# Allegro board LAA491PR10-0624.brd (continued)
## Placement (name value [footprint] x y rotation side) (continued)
PC521  -  [C_0402]  116.02 144.14 90 bottom
PC522  -  [C_0402]  85.46 139.95 180 bottom
PC523  -  [C_0402]  83.49 135.41 90 top
PC600  -  [C_0805]  217.87 98.24 0 top
PC601  -  [C_0402]  216.62 92.66 0 bottom
PC602  -  [C_0805]  217.87 96.21 0 top
PC603  -  [C_0402]  220.06 93.37 270 top
PC604  -  [C_0402]  222.16 88.02 180 bottom
PC605  -  [C_0805]  217.14 89.96 90 bottom
PC701  -  [C_0603]  143.03 169.17 270 bottom
PC702  -  [C_0402]  143.81 166.63 180 bottom
PC703  -  [C_0805]  157.7 166.24 0 top
PC704  -  [C_0805]  157.7 164.46 0 top
PC705  -  [C_0402]  158 168.86 0 top
PC706  -  [C_0603]  157.83 167.78 0 top
PC707  -  [C_0603]  167.42 167.65 0 bottom
PC708  -  [C_0402]  166.4 167.46 90 bottom
PC709  -  [C_0603]  164.68 172.54 180 top
PC710  -  [C_0603]  163.92 167.08 180 top
PC711  -  [C_0402]  172.25 168.09 180 top
PC712  -  [C_0805]  146.63 179.72 0 top
PC713  -  [C_0805]  146.63 181.43 0 top
PC714  -  [C_0805]  145.93 175.97 0 top
PC715  -  [C_0402]  154.13 176.5 0 top
PC716  -  [C_0805]  146.63 183.14 0 top
PC717  -  [C_0402]  167.75 165.94 180 top
PC718  -  [C_0805]  145.93 174.25 0 top
PC719  -  [C_0402]  169.64 174.06 270 top
PC720  -  [C_0402]  195.61 51.71 270 bottom
PC721  -  [C_0603]  162.53 168.35 0 top
PC722  -  [C_0402]  167.73 175.14 0 top
PC723  -  [C_0402]  171.99 177.11 180 top
PC724  -  [C_EEEFZ1E101P]  157.1 164.03 0 bottom
PC803  -  [C_0603]  207.1 61.73 90 bottom
PC804  -  [C_0805]  212.73 71.83 0 top
PC805  -  [C_0805]  212.73 69.54 0 top
PC806  -  [C_0402]  204.23 51.95 0 bottom
PC807  -  [C_0603]  202.47 61.67 0 bottom
PC808  -  [C_0805]  212.73 67.26 0 top
PC809  -  [C_0402]  201.51 54.63 270 bottom
PC810  -  [C_0603]  201.51 57.48 180 top
PC811  -  [C_0603]  205.32 58.94 0 top
PC813  -  [C_0402]  205.32 55.27 270 top
PC814  -  [C_0402]  204.23 51.06 0 bottom
PC815  -  [C_0603]  208.56 62.81 0 top
PC816  -  [C_0402]  201.58 55.5 90 top
PC817  -  [C_0402]  201.58 51.05 90 bottom
PC818  -  [C_0402]  206.04 53.73 180 bottom
PC819  -  [C_0402]  199.11 59.26 180 bottom
PC820  -  [C_0402]  199.11 58.37 180 bottom
PC821  -  [C_0402]  201.59 54.62 180 top
PC831  -  [C_0402]  213.38 74.05 0 top
PC832  -  [C_0402]  213.38 73.16 0 top
PC835  -  [C_0603]  194.53 89.16 90 top
PC836  -  [C_D1]  204.04 84.58 0 top
PC837  -  [C_D1]  200.82 86.25 270 bottom
PC838  -  [C_D1]  195.99 84.68 270 bottom
PC839  -  [C_D1]  191.23 84.68 270 bottom
PC840  -  [C_0402]  181.44 122.2 0 top
PC841  -  [C_0402]  181.5 117.69 0 top
PC842  -  [C_0402]  182.08 118.93 90 top
PC843  -  [C_0402]  179.54 117.69 0 top
PC844  -  [C_0402]  177.34 117.24 180 top
PC845  -  [C_0402]  177.34 118.7 180 top
PC846  -  [C_0402]  176.49 120.67 0 top
PC847  -  [C_0402]  179.59 115.96 0 top
PC848  -  [C_0402]  181.37 115.96 0 top
PC849  -  [C_0402]  173.88 102.2 270 bottom
PC850  -  [C_0402]  178.21 119.85 270 top
PC851  -  [C_0402]  179.09 119.45 0 top
PC852  -  [C_0402]  178.73 115.71 180 top
PC853  -  [C_0402]  175.43 120.67 180 top
PC854  -  [C_0402]  174.46 117.24 0 top
PC855  -  [C_0402]  175.43 122.13 180 top
PC856  -  [C_0402]  179.28 122.2 0 top
PC857  -  [C_0402]  179.34 123.66 0 top
PC858  -  [C_0402]  181.44 123.66 0 top
PC859  -  [C_0402]  179.28 120.74 0 top
PC860  -  [C_0402]  181.44 120.74 0 top
PC861  -  [C_0402]  176.95 115.71 180 top
PC862  -  [C_0402]  178.2 112.47 0 top
PC863  -  [C_0402]  175.17 115.71 180 top
PC864  -  [C_0402]  176.36 122.13 0 top
PC865  -  [C_0402]  176.49 123.63 0 top
PC866  -  [C_0402]  174.46 118.7 0 top
PC867  -  [C_0603]  192.82 89.16 90 top
PC868  -  [C_0603]  196.31 89.16 90 top
PC869  -  [C_0402]  207.62 56.21 180 top
PC870  -  [C_0603]  198.02 89.16 90 top
PC871  -  [C_0402]  173.58 117.55 90 top
PC872  -  [C_0402]  172.18 117.02 90 top
PC873  -  [C_0402]  172.18 119.73 270 top
PC901  -  [C_0805]  97.44 122.73 90 top
PC902  -  [C_0805]  100.3 122.67 90 top
PC903  -  [C_0805]  102.77 122.67 90 top
PC904  -  [C_0805]  105.31 122.67 90 top
PC905  -  [C_0805]  107.79 122.67 90 top
PC906  -  [C_0805]  110.33 122.67 90 top
PC907  -  [C_0805]  112.81 122.67 90 top
PC908  -  [C_0805]  96.93 117.9 90 top
PC909  -  [C_0805]  100.65 137.55 0 top
PC910  -  [C_0805]  96.87 114.79 90 top
PC911  -  [C_0805]  97.35 135.33 0 top
PC912  -  [C_0805]  110.81 135.33 0 top
PC913  -  [C_0805]  110.75 137.49 0 top
PC914  -  [C_0805]  107.45 135.33 0 top
PC915  -  [C_0805]  107.38 137.49 0 top
PC916  -  [C_0805]  104.08 135.33 0 top
PC917  -  [C_0805]  100.71 135.33 0 top
PC918  -  [C_0805]  110.81 133.93 0 bottom
PC919  -  [C_0805]  107.45 133.93 0 bottom
PC920  -  [C_0805]  104.08 133.93 0 bottom
PC921  -  [C_0805]  100.71 133.93 0 bottom
PC922  -  [C_0805]  103.95 137.55 0 top
PC923  -  [C_0805]  97.35 133.93 0 bottom
PC1001  -  [C_0402]  39.14 105.74 270 bottom
PC1002  -  [C_0805]  42.95 110.53 90 bottom
PC1003  -  [C_0402]  38 116.41 270 bottom
PC1004  -  [C_0402]  36.48 105.74 270 bottom
PC1005  -  [C_0805]  40.83 115.25 0 bottom
PC1100  -  [C_0402]  178.64 173.37 0 top
PC1101  -  [C_0402]  178.64 174.25 0 top
PC1102  -  [C_0805]  178.82 175.59 0 top
PC1103  -  [C_0603]  183.16 170.25 90 top
PC1104  -  [C_0402]  188.19 172.03 180 bottom
PC1105  -  [C_0603]  183.67 173.05 90 top
PC1106  -  [C_0402]  181.45 170.11 90 top
PC1108  -  [C_APXK6R3ARA221MF451]  182.65 167.14 0 bottom
PC1200  -  [C_0402]  183.99 186.18 90 bottom
PC1201  -  [C_0805]  190.85 185.34 90 bottom
PC1202  -  [C_0805]  177.8 177.49 0 bottom
PC1203  -  [C_0402]  175.88 182.71 180 bottom
PC1204  -  [C_0805]  177.8 179.21 0 bottom
PC1205  -  [C_0603]  176.37 183.78 180 bottom
PC1206  -  [C_0805]  189.07 185.34 90 bottom
PC1207  -  [C_0805]  189.07 177.01 270 bottom
PC1209  -  [C_0402]  175.88 181.82 180 bottom
PC1210  -  [C_0603]  175.81 186.52 270 bottom
PC1211  -  [C_0805]  190.78 177.01 270 bottom
PC1212  -  [C_0603]  181.13 176.16 90 bottom
PC1213  -  [C_0603]  178.22 185.12 90 bottom
PC1214  -  [C_0402]  173.46 184.16 180 bottom
PC1300  -  [C_0805]  199.1 73.38 270 top
PC1301  -  [C_0805]  195 60.72 180 bottom
PC1302  -  [C_0402]  194.67 62.62 180 top
PC1303  -  [C_0805]  193.64 73.38 270 top
PC1304  -  [C_0402]  197.15 65.03 180 top
PC1305  -  [C_0805]  197.32 73.38 270 top
PC1306  -  [C_0402]  197.77 63.52 270 top
PC1307  -  [C_0402]  196.94 65.11 270 bottom
PC1308  -  [C_0805]  195.55 73.38 270 top
PD1  -  [IP4223CZ6_SO6]  142.24 185.05 270 bottom
PD2  -  [TVNST52302AB0_SOT523-3]  139.74 181.94 180 top
PD3  -  [TVNST52302AB0_SOT523-3]  144.07 185.19 270 bottom
PD101  -  [L03ESDL5V0CG3-2_SOT-523-3]  122.63 13.98 90 top
PD701  -  [RB751V-40_SOD323-2]  162.54 171.02 0 top
PH1  -  [R_0402]  106.19 113.74 0 top
PH501  -  [R_0402]  95.58 143.46 0 bottom
PH502  -  [R_0402]  111.93 144.16 180 bottom
PH800  -  [R_0402]  203.86 79.08 270 bottom
PJP100  -  [JUMP_43X118]  134.78 13.39 270 bottom
PJP101  -  [JUMP_43X118]  122.58 13.51 270 bottom
PJP102  -  [JUMP_43X118]  140.05 13.39 270 bottom
PJP103  -  [JUMP_43X118]  117.31 13.51 270 bottom
PJP200  -  [JUMP_43X118]  149.32 27.84 90 top
PJP201  -  [JUMP_43X118]  144.81 27.59 90 bottom
PJP203  -  [JUMP_43X39]  155.03 29.36 270 bottom
PJP300  -  [JUMP_43X118]  143.67 140.45 270 top
PJP400  -  [JUMP_43X79]  108.3 20.35 90 bottom
PJP401  -  [JUMP_43X79]  112.11 31.27 90 bottom
PJP600  -  [JUMP_43X79]  213.98 90.82 0 bottom
PJP601  -  [JUMP_43X79]  215.29 96.76 270 top
PJP1000  -  [JUMP_43X79]  42.19 104.48 90 bottom
PJP1001  -  [JUMP_43X79]  36.65 115.95 180 top
PJP1100  -  [JUMP_43X118]  182.78 162.32 270 bottom
PJP1101  -  [JUMP_43X118]  188.12 162.32 270 bottom
PJP1200  -  [JUMP_43X118]  192.27 181.37 0 bottom
PJP1300  -  [JUMP_43X79]  195.74 76.19 270 top
PJP1301  -  [JUMP_43X79]  194.66 58.76 270 bottom
PJPDC  -  [ACES_50299-00501-003_5P]  136.9 178.4 270 bottom
PL1  -  [CHT_C8BBPH853025_2P]  140.43 174 270 bottom
PL2  -  [CHT_C8BBPH853025_2P]  132.93 182.51 180 bottom
PL3  -  [CHENG_SMB3025500YA_2P]  155.86 180.26 90 bottom
PL4  -  [CHT_C8BBPH853025_2P]  132.87 166.13 180 bottom
PL100  -  [VISHAY_IHLP-2525CZ-01_2P]  135.35 25.41 0 bottom
PL101  -  [VISHAY_IHLP-2525CZ-01_2P]  120.17 25.57 180 bottom
PL102  -  [CYNTE_PCMB053T-1R0MS_2P]  127.73 31.78 270 bottom
PL200  -  [TAI-T_VMPI0703AR-1R0M-Z01_2P]  145.4 15.12 0 bottom
PL201  -  [L_1812-1806]  165.32 20.69 270 bottom
PL301  -  [CYNTE_PCMB063T-1R0MS_2P]  144.08 150.59 270 bottom
PL302  -  [L_1812-1806]  134.42 158.32 0 bottom
PL400  -  [TAIYO_NRS4018T1R0NDGJ_2P]  107.58 28.97 90 bottom
PL501  -  [L_1812-1806]  135.09 146.53 90 bottom
PL502  -  [TOKO_FDUE1040J-H-R36M-P3_4P]  109.67 140.15 180 bottom
PL600  -  [TAIYO_NRS4018T1R0NDGJ_2P]  219.55 94.6 90 bottom
PL701  -  [TOKO_FDVE1040-H-2R2M-P3_2P]  155.38 172.6 180 bottom
PL702  -  [CYNTE_PCMB053T-1R0MS_2P]  146.89 163.46 0 bottom
PL800  -  [L_1812-1806]  217.55 77.92 180 top
PL802  -  [MAG_MMD-12CE-R36M-M1L_2P]  211.17 74.49 90 bottom
PL1100  -  [TAI-T_HCB2012KF-121T50_2P]  175.16 177.38 90 top
PL1101  -  [PANAS_ETQP3W2R2WFN_2P]  176.62 169.83 90 bottom
PL1200  -  [CYNTE_PCMB063T-1R0MS_2P]  183.29 181.24 0 bottom
PL1201  -  [L_1812-1806]  171.44 178.76 0 bottom
PL1300  -  [VISHAY_IHLP-2525CZ-01_2P]  195.55 71.38 90 bottom
PQ1  -  [2N7002DW-T-R7_SOT363-6]  128.22 173.52 0 top
PQ2  -  [2N7002DW-T-R7_SOT363-6]  128.9 168.81 270 top
PQ3  -  [2N7002DW-T-R7_SOT363-6]  128.96 163.6 270 top
PQ4  -  [SSM3K7002FU_SC70-3]  128.17 179.34 0 top
PQ5  -  [RHU002N06_SOT323-3]  133.89 187.37 0 bottom
PQ6  -  [FDV301N_NL_SOT23-3]  128.97 186.57 90 bottom
PQ101  -  [SIS412DN-T1-GE3_POWERPAK8-5]  133.1 26.55 90 top
PQ102  -  [SIS412DN-T1-GE3_POWERPAK8-5]  130.23 24.72 270 top
PQ103  -  [SIS412DN-T1-GE3_POWERPAK8-5]  121.78 28.7 270 top
PQ104  -  [SIS412DN-T1-GE3_POWERPAK8-5]  124.65 22.93 90 top
PQ200  -  [SIS412DN-T1-GE3_POWERPAK8-5]  154.68 16.29 90 bottom
PQ201  -  [SIS412DN-T1-GE3_POWERPAK8-5]  157.04 14.46 270 bottom
PQ701  -  [CSD87312Q3E_SON8-4]  140.24 167.98 0 bottom
PQ702  -  [AO4407AL_SO8]  147.12 178.89 90 bottom
PQ703  -  [MDU1516URH_POWERDFN56-8-5]  156.11 169.3 180 top
PQ704  -  [MDU1516URH_POWERDFN56-8-5]  149.77 169.32 180 top
PQ705  -  [MDU1511RH_POWERDFN56-8-5]  159.54 171.17 90 top
PQ706  -  [SSM3K7002FU_SC70-3]  135.79 168.22 180 top
PQ708  -  [SSM3K7002FU_SC70-3]  171.48 173.11 0 top
PQ800  -  [SIR472DP-T1-GE3_POWERPAK8-5]  205.77 69.54 270 top
PQ801  -  [SIR818DP-T1_POWERPAK-SO8-5]  214.09 65.47 270 bottom
PQ802  -  [SIR818DP-T1_POWERPAK-SO8-5]  214.09 71.26 270 bottom
PQ803  -  [SIR472DP-T1-GE3_POWERPAK8-5]  205.77 75.38 270 top
PQ1100  -  [SIS412DN-T1-GE3_POWERPAK8-5]  175.38 172.25 0 top
PQ1101  -  [SIS412DN-T1-GE3_POWERPAK8-5]  180.28 174.79 270 bottom
PQ1201  -  [2N7002W-T-R7_SOT323-3]  173.45 186.99 0 bottom
PR1  -  [R_0402]  128.32 171.12 0 top
PR2  -  [R_0402]  130.09 171.12 270 top
PR3  -  [R_0402]  132.35 185.62 0 top
PR4  -  [R_0402]  130.57 185.62 0 top
PR5  -  [R_1206]  131.27 175.59 270 top
PR6  -  [R_0402]  132.5 182.7 180 top
PR7  -  [R_0402]  128.86 177.49 0 top
PR8  -  [R_0402]  134.22 187.46 180 top
PR9  -  [R_0402]  134.28 182.7 180 top
PR10  -  [R_0402]  129.77 176.6 180 top
PR15  -  [R_0402]  137.62 184.73 90 bottom
PR16  -  [R_0402]  136.76 184.92 180 bottom
PR17  -  [R_0402]  138.55 184.73 90 bottom
PR18  -  [R_0402]  141.88 183.65 0 top
PR20  -  [R_0402]  141.88 184.54 0 top
PR23  -  [R_0402]  129.94 179.91 0 top
PR24  -  [R_0402]  181.96 45.02 90 bottom
PR26  -  [R_0402]  130.85 181.68 180 top
PR27  -  [R_0402]  129.11 178.89 0 top
PR28  -  [R_0402]  128.38 166.38 180 top
PR29  -  [R_0402]  127.65 170 0 top
PR30  -  [R_0402]  127.54 161.8 90 top
PR31  -  [R_0402]  131.98 167.7 90 top
PR32  -  [R_0402]  132.11 162.71 270 top
PR33  -  [R_0402]  130.51 166.32 0 top
PR100  -  [R0402_0OHM]  120.98 13.13 180 top
PR101  -  [R0402_0OHM]  120.98 14.91 180 top
PR102  -  [R_0402]  120.98 14.02 180 top
PR103  -  [R_0402]  132.44 16.68 180 top
PR104  -  [R_0402]  126.71 12.98 270 top
PR105  -  [R_0402]  125.82 12.98 270 top
PR106  -  [R_0402]  125.72 12.99 270 bottom
PR107  -  [R_0402]  130.71 12.06 90 top
PR108  -  [R_0402]  131.6 12.98 270 top
PR109  -  [R_0402]  128.93 12.06 90 top
PR111  -  [R_0402]  124.12 17.28 180 top
PR112  -  [R_1206]  119.98 25.06 270 top
PR113  -  [R_1206]  134.97 24.87 270 top
PR114  -  [R_0402]  124.12 15.5 180 top
PR200  -  [R_0603]  154.85 22.95 90 bottom
PR201  -  [R0402_0OHM]  162.92 25.22 180 bottom
PR202  -  [R0402_0OHM]  162.92 27 180 bottom
PR203  -  [R_1206]  161.32 10.74 0 bottom
PR204  -  [R_0402]  161.47 29.11 180 bottom
PR205  -  [R_0402]  158.6 20.28 90 bottom
PR206  -  [R_0603]  162.09 21.42 270 bottom
PR207  -  [R_0402]  161.47 28.22 180 bottom
PR208  -  [R_0402]  162.92 23.44 180 bottom
PR300  -  [R0402_0OHM]  148.17 148.34 0 bottom
PR301  -  [R_0402]  148.17 149.23 0 bottom
PR302  -  [R_1206]  139.54 146.56 90 bottom
PR303  -  [R0603_0OHM]  147.04 156.85 0 bottom
PR304  -  [R_0402]  149.08 152.78 180 bottom
PR305  -  [R_0402]  148.62 153.72 90 bottom
PR306  -  [R_0402]  148.17 151.89 0 bottom
PR307  -  [R_0402]  149.39 155.5 90 bottom
PR308  -  [R_0402]  149.08 151.01 180 bottom
PR401  -  [R0402_0OHM]  113.68 26.85 270 bottom
PR402  -  [R_0402]  111.9 23.78 90 bottom
PR403  -  [R_0402]  112.79 24.69 270 bottom
PR404  -  [R_0402]  112.79 26.85 270 bottom
PR405  -  [R_0603]  108.34 26.97 180 bottom
PR501  -  [R_0402]  88.61 141.22 90 bottom
PR502  -  [R_0402]  85.94 141.22 90 bottom
PR503  -  [R_0402]  88.48 138.94 90 top
PR504  -  [R_0402]  86.83 141.22 90 bottom
PR505  -  [R_0402]  86.71 138.94 90 top
PR506  -  [R_0402]  85.82 138.94 90 top
PR507  -  [R_0402]  87.72 141.22 90 bottom
PR508  -  [R_0402]  91.66 142.19 270 bottom
PR509  -  [R_0402]  87.6 138.94 90 top
PR510  -  [R_0402]  87.01 137.23 0 top
PR512  -  [R_0402]  89.37 138.94 90 top
PR513  -  [R_0402]  91.15 138.94 90 top
PR514  -  [R_0402]  90.77 141.29 90 bottom
PR515  -  [R_0402]  92.98 141.74 0 bottom
PR516  -  [R_0603]  83.98 135.77 0 bottom
PR517  -  [R_0402]  92.98 140.85 0 bottom
PR518  -  [R_0402]  92.93 143.06 90 bottom
PR519  -  [R_0603]  88.87 131.89 90 bottom
PR522  -  [R0402_0OHM]  85.46 139.06 180 bottom
PR524  -  [R_0402]  84.55 137.28 0 bottom
PR526  -  [R_0402]  87.79 132.59 90 bottom
PR528  -  [R_0402]  86.9 132.59 90 bottom
PR529  -  [R_0402]  92.66 132.6 0 bottom
PR530  -  [R_0402]  84.54 134.69 0 bottom
PR531  -  [R_0402]  90.9 132.66 90 bottom
PR532  -  [R_0402]  93.58 133.49 180 bottom
PR533  -  [R_0402]  85.47 134.5 180 top
PR534  -  [R_1206]  108.42 143.2 0 top
PR535  -  [R0402_0OHM]  85.46 138.17 180 bottom
PR536  -  [R_0603]  116.77 140.05 0 bottom
PR540  -  [R_0402]  84.56 135.39 0 top
PR601  -  [R0402_0OHM]  218.29 93.36 180 top
PR602  -  [R_0402]  221.26 89.79 90 bottom
PR603  -  [R_0402]  222.16 88.91 180 bottom
PR604  -  [R_0402]  219.17 93.37 270 top
PR605  -  [R_0603]  216.06 95.13 270 bottom
PR701  -  [R_0402]  142.9 163.89 90 bottom
PR702  -  [R_1206_4P-D]  139.7 162.19 0 bottom
PR703  -  [R_0402]  143.79 164.81 270 bottom
PR704  -  [R0402_0OHM]  166.78 165.95 270 bottom
PR705  -  [R_1206]  164.49 163.08 90 top
PR706  -  [R_0402]  147.36 183.91 180 bottom
PR707  -  [R_0402]  169.07 164.97 90 top
PR708  -  [R0402_0OHM]  167.67 173.04 90 top
PR709  -  [R_0603]  163.92 169.56 180 top
PR710  -  [R0402_0OHM]  168.56 173.04 90 top
PR711  -  [R_0402]  172.25 167.21 180 top
PR712  -  [R_0402]  170.02 165.88 270 top
PR713  -  [R_0402]  171.34 171.65 0 top
PR714  -  [R0402_0OHM]  172.25 170.76 180 top
PR715  -  [R0402_0OHM]  172.25 169.87 180 top
PR716  -  [R_1206_4P-D]  143.73 176.64 90 bottom
PR717  -  [R0402_0OHM]  167.67 165.95 270 bottom
PR720  -  [R_1206]  138.21 169.94 180 top
PR721  -  [R_0402]  143.81 165.68 180 bottom
PR722  -  [R_1206]  156.37 177.01 0 top
PR723  -  [R_0402]  171.34 166.32 0 top
PR724  -  [R_0402]  171.07 176.22 0 top
PR802  -  [R0603_0OHM]  201.39 60.08 90 bottom
PR803  -  [R0402_0OHM]  209.91 56.02 180 bottom
PR804  -  [R0402_0OHM]  206.71 57.1 0 top
PR805  -  [R_1206]  211.17 62.68 0 top
PR806  -  [R0402_0OHM]  209.91 56.91 180 bottom
PR807  -  [R0402_0OHM]  209.91 58.68 180 bottom
PR808  -  [R_0402]  209.91 54.24 180 bottom
PR809  -  [R0402_0OHM]  209.91 57.8 180 bottom
PR810  -  [R0402_0OHM]  208.7 59 180 top
PR811  -  [R0402_0OHM]  206.96 60.46 0 top
PR812  -  [R0402_0OHM]  209.91 59.57 180 bottom
PR813  -  [R_0402]  203.37 51.95 180 bottom
PR814  -  [R0603_0OHM]  205.9 61.73 90 bottom
PR815  -  [R_0402]  206.72 54.35 90 top
PR816  -  [R_0402]  199.11 56.59 180 bottom
PR817  -  [R_0402]  206.04 52.84 180 bottom
PR818  -  [R_0402]  203.37 51.06 180 bottom
PR819  -  [R_0402]  207.79 58.11 0 top
PR820  -  [R_0402]  205.32 53.49 270 top
PR821  -  [R_0402]  204.25 53.74 270 bottom
PR822  -  [R_0603]  201.51 58.68 180 bottom
PR823  -  [R0603_0OHM]  201.51 58.68 180 top
PR824  -  [R_0402]  201.58 60.67 270 top
PR825  -  [R_0402]  201.59 55.51 180 bottom
PR826  -  [R_0402]  213.91 59.51 180 bottom
PR827  -  [R_0402]  199.11 57.48 180 bottom
PR828  -  [R_0402]  209.64 58.1 90 top
PR829  -  [R_0402]  199.1 61.05 270 bottom
PR830  -  [R0402_0OHM]  198.21 61.05 270 bottom
PR833  -  [R_0402]  200.69 56.41 270 top
PR834  -  [R_0402]  211.22 59.57 0 bottom
PR835  -  [R_0402]  213.91 57.99 180 bottom
PR836  -  [R_0402]  211.22 57.99 0 bottom
PR837  -  [R_0402]  213.91 57.1 180 bottom
PR838  -  [R_0402]  211.22 57.1 0 bottom
PR839  -  [R_0402]  213.91 55.57 180 bottom
PR840  -  [R_0402]  211.22 55.57 0 bottom
PR842  -  [R_0402]  209 55.13 0 bottom
PR845  -  [R0402_0OHM]  200.63 54.63 270 bottom
PR846  -  [R0402_0OHM]  203.37 53.73 180 bottom
PR1001  -  [R_0402]  37.11 116.41 270 bottom
PR1002  -  [R_0402]  36.22 115.49 90 bottom
PR1003  -  [R_0402]  37.37 104.82 90 bottom
PR1004  -  [R_0402]  38.26 105.74 270 bottom
PR1101  -  [R_0603]  185.07 169.17 180 top
PR1102  -  [R_0402]  187.28 171.14 0 bottom
PR1103  -  [R0402_0OHM]  189.89 173.19 270 top
PR1104  -  [R_1206]  177.58 170.44 0 top
PR1105  -  [R_0402]  188.19 173.81 180 bottom
PR1107  -  [R_0402]  189.89 172.87 270 bottom
PR1108  -  [R_0402]  188.19 172.92 180 bottom
PR1110  -  [R_0402]  189.21 169.68 180 top
PR1200  -  [R0603_0OHM]  177.01 185.12 90 bottom
PR1201  -  [R_0402]  184.88 186.18 90 bottom
PR1202  -  [R_0402]  182.21 186.18 90 bottom
PR1203  -  [R_0402]  181.32 187.09 270 bottom
PR1204  -  [R_0402]  178.36 187.47 180 bottom
PR1206  -  [R0402_0OHM]  185.77 186.18 90 bottom
PR1207  -  [R_1206]  185.13 176.67 180 bottom
PR1208  -  [R_0402]  180.45 188.22 180 bottom
PR1209  -  [R_0402]  179.54 185.54 90 bottom
PR1210  -  [R0402_0OHM]  179.53 187.34 0 bottom
PR1211  -  [R_0402]  176.06 187.46 180 bottom
PR1212  -  [R_0402]  172.55 183.27 0 bottom
PR1213  -  [R_0402]  170.72 184.17 270 bottom
PR1214  -  [R_0402]  171.61 183.26 90 bottom
PR1300  -  [R_0402]  197.84 65.99 180 bottom
PR1301  -  [R_0402]  195.99 62.61 90 top
PR1302  -  [R_0402]  196.88 63.52 270 top
PR1303  -  [R_1206]  196.63 68.91 270 top
PR1304  -  [R_0402]  197.9 65.11 270 bottom
PU100  -  [TPS51225CRUKR_QFN20_3X3]  127.03 14.52 0 top
PU200  -  [RT8207MZQW_WQFN20_3X3]  157.71 26.38 0 bottom
PU300  -  [SY8206DQNC_QFN10_3X3]  145.59 153.63 90 bottom
PU400  -  [SY8003DFC_DFN8_2X2]  110.87 24.21 180 bottom
PU501  -  [TPS51622RSM_QFN32_4X4]  87.18 136.02 90 bottom
PU502  -  [CSD97374CQ4M_SON8_3P5X4P5-S]  111.9 139.63 90 bottom
PU600  -  [SY8003DFC_DFN8_2X2]  220.04 90.16 180 bottom
PU701  -  [BQ24738RGRR_QFN20_3P5X3P5]  166.99 167.7 0 top
PU800  -  [ISL62881HRZ-T_QFN28_4X4]  206.59 55.46 180 bottom
PU1000  -  [APL5930KAI-TRG_SO8]  37.49 113.07 0 bottom
PU1100  -  [TPS51212DSCR_SON10_3X3]  188.26 171.29 90 top
PU1200  -  [SY8206DQNC_QFN10_3X3]  180.29 183.54 180 bottom
PU1300  -  [SY8036DBC_DFN10_3X3]  193.66 65.57 0 bottom
Q1  -  [2N7002K_SOT23-3]  41.66 116.71 270 top
Q2  -  [DMN66D0LDW-7_SOT363-6]  17.04 115.46 270 bottom
Q3  -  [2N7002K_SOT23-3]  19.56 116.84 270 top
Q4  -  [2N7002K_SOT23-3]  19.37 117.41 90 bottom
Q8  -  [2N7002K_SOT23-3]  87.21 23.02 180 top
Q25  -  [DMG2301U-7_SOT23-3]  23.78 111.99 180 bottom
Q2307  -  [2N7002K_SOT23-3]  182.97 60.17 180 top
Q2308  -  [2N7002K_SOT23-3]  147.9 121.17 270 top
QA5  -  [DMN66D0LDW-7_SOT363-6]  25.85 27.08 270 bottom
QA6  -  [DMN66D0LDW-7_SOT363-6]  15.93 20.7 90 bottom
QC1  -  [DMN66D0LDW-7_SOT363-6]  144.74 110.07 0 bottom
QC3  -  [2N7002K_SOT23-3]  134.62 130.95 180 bottom
QD2  -  [BSS138-G_SOT23-3]  48.7 64.91 90 top
QD18  -  [2N7002K_SOT23-3]  57.9 16.58 90 top
QD19  -  [2N7002K_SOT23-3]  61.48 16.6 270 top
QD20  -  [2N7002K_SOT23-3]  70.62 15.07 0 top
QH1  -  [DMN66D0LDW-7_SOT363-6]  148.21 115.18 270 bottom
QM30  -  [2N7002K_SOT23-3]  102.42 147.33 90 top
QS2  -  [SI3456BDV-T1-E3_TSOP6]  220.85 121.09 0 bottom
QS3  -  [2N7002KW_SOT323-3]  221.49 125.83 0 bottom
QV14  -  [DMN66D0LDW-7_SOT363-6]  188.48 101.22 0 bottom
QV15  -  [DMN66D0LDW-7_SOT363-6]  178.54 93.83 180 top
QV22  -  [AP2301GN-HF_SOT23-3]  184.15 93.73 90 bottom
QV24  -  [2N7002K_SOT23-3]  179 90.24 270 bottom
QV25  -  [2N7002K_SOT23-3]  174.36 90.05 270 bottom
QV28  -  [2N7002K_SOT23-3]  183.16 90.53 0 top
QX1  -  [2N7002KW_SOT323-3]  216.84 176.48 90 top
QX2  -  [SI3457CDV-T1-GE3_TSOP6]  223.09 176.67 180 top
QX6  -  [DMN66D0LDW-7_SOT363-6]  196.11 163.13 90 top
R1  -  [R_0402]  93.64 134.06 180 top
R2  -  [R_0402]  91.86 134.06 180 top
R3  -  [R_0603]  14.7 110.11 180 top
R4  -  [R_0603]  13.05 114.3 180 top
R6  -  [R_0402]  16.41 113.36 270 top
R10  -  [R_0402]  85.69 24.72 270 top
R12  -  [R_0402]  16.41 108.02 270 top
R13  -  [R_0402]  16.41 109.8 270 top
R15  -  [R_0402]  39.91 117.17 270 top
R16  -  [R_0402]  87.84 19.19 0 top
R17  -  [R_0402]  40.87 118.24 180 top
R18  -  [R_0402]  14.43 97.41 0 bottom
R19  -  [R_0402]  18.96 96.9 90 bottom
R20  -  [R_0402]  14.43 98.3 0 bottom
R21  -  [R_0402]  20.09 108.76 90 bottom
R22  -  [R_0402]  25.05 108.76 90 bottom
R23  -  [R_0603]  20.29 113.98 270 bottom
R24  -  [R_0402]  22.38 109.68 270 top
R25  -  [R_0402]  21.49 109.68 270 top
R26  -  [R_0402]  15.35 106.38 180 bottom
R27  -  [R_0402]  18.19 113.74 270 bottom
R28  -  [R_0402]  18.19 114.6 90 bottom
R29  -  [R_0402]  15.35 104.9 180 bottom
R30  -  [R_0402]  15.35 103.38 180 bottom
R31  -  [R_0402]  12.22 100.76 90 bottom
R32  -  [R_0402]  15.35 100.96 180 bottom
R33  -  [R_0402]  12.35 104.38 90 bottom
R34  -  [R_0402]  12.22 107.14 270 bottom
R35  -  [R_0402]  25.24 96.82 90 bottom
R36  -  [R_0402]  26.25 99.17 90 bottom
R37  -  [R_0402]  14.43 99.19 0 bottom
R38  -  [R_0402]  21.12 114.93 180 bottom
R39  -  [R_0402]  20.15 114.43 0 top
R40  -  [R_0402]  24.16 108.76 90 bottom
R41  -  [R_0402]  14.43 100.07 0 bottom
R42  -  [R_0402]  19.21 108.76 90 bottom
R159  -  [R_0402]  147.53 102.56 0 top
R245  -  [R_0603]  93.12 129.93 90 bottom
R248  -  [R0402_0OHM]  80.85 117.8 0 bottom
R250  -  [R_0402]  91.98 122.11 90 top
R251  -  [R0402_0OHM]  90.52 129.69 270 bottom
R252  -  [R_0402]  80.85 118.69 0 bottom
R253  -  [R_0402]  81.77 120.6 180 bottom
R254  -  [R_0402]  84.12 118.69 180 bottom
R255  -  [R_0402]  83.2 120.98 0 bottom
R256  -  [R_0402]  79.92 119.58 0 bottom
R257  -  [R0402_0OHM]  79.92 120.53 180 bottom
R264  -  [R0603_0OHM]  150.97 104.66 180 top
R265  -  [R0402_0OHM]  118.33 98.19 270 top
R267  -  [R0805_0OHM]  123.83 140.85 0 bottom
R286  -  [R_0402]  92.04 129.69 270 bottom
R416  -  [R0402_0OHM]  143.04 19.76 180 bottom
R2313  -  [R_0402]  96.8 25.59 90 top
R2314  -  [R_0603]  184.62 62.49 270 top
R2315  -  [R_0603]  146.9 124.09 270 top
R2318  -  [R_0402]  93.44 25.65 90 top
R2329  -  [R_0402]  140.87 109.06 0 bottom
R2330  -  [R_0402]  135.28 103.65 270 bottom
R2331  -  [R_0402]  147.04 109 270 bottom
R2332  -  [R_0402]  147.93 110.06 180 bottom
R2333  -  [R_0402]  142.55 115.86 180 bottom
R2334  -  [R_0402]  142.55 116.75 180 bottom
R2335  -  [R_0402]  142.55 117.63 180 bottom
R2336  -  [R_0402]  125.72 96.24 90 top
R2337  -  [R_0402]  134.01 99.65 270 bottom
R2338  -  [R_0402]  133.13 99.65 270 bottom
R2341  -  [R_0402]  75.29 114.06 180 top
R2346  -  [R_0402]  79.91 122.5 90 bottom
R2347  -  [R_0402]  43.97 63.82 90 top
R2348  -  [R_0402]  43.08 62.98 270 top
R2349  -  [R_0402]  43.97 62.98 270 top
R2350  -  [R_0402]  42.19 62.98 270 top
R2351  -  [R_0402]  44.86 63.82 90 top
R2352  -  [R_0402]  41.3 62.98 270 top
R2354  -  [R_0402]  187.42 32.7 90 top
R2355  -  [R_0402]  32.15 20.52 0 top
R2356  -  [R_0402]  127.24 97.04 90 bottom
R2357  -  [R_0402]  130.9 97.48 180 bottom
R2358  -  [R_0402]  129.05 97.04 90 bottom
R2359  -  [R_0402]  128.16 97.04 90 bottom
RA1  -  [R_0402]  30.57 28.28 270 top
RA2  -  [R_0402]  21.84 26.56 0 bottom
RA3  -  [R_0402]  28.73 23.56 90 bottom
RA4  -  [R0402_0OHM]  30.57 25.59 90 top
RA5  -  [R_0402]  17.62 25.49 270 bottom
RA6  -  [R_0402]  15.78 25.49 270 bottom
RA7  -  [R_0402]  16.69 25.49 270 bottom
RA8  -  [R_0402]  25.66 14.74 90 top
RA9  -  [R_0402]  24.78 14.74 90 top
RA19  -  [R_0402]  36.62 23.63 180 top
RA29  -  [R0603_0OHM]  23.91 21.6 0 bottom
RA30  -  [R0603_0OHM]  26.57 23.76 270 bottom
RA31  -  [R0603_0OHM]  23.27 26.81 90 top
RA32  -  [R0603_0OHM]  26.84 12.05 0 top
RA51  -  [R_0402]  29.68 25.59 90 top
RA53  -  [R_0402]  15.84 23.37 90 top
RA55  -  [R_0402]  24.04 11.61 0 bottom
RA56  -  [R_0402]  24.04 12.49 0 bottom
RA79  -  [R_0402]  33.93 24.52 0 top
RA80  -  [R_0402]  21.82 20.14 180 bottom
RA81  -  [R_0402]  34.84 25.41 180 top
RA82  -  [R_0402]  21.82 21.03 180 bottom
RA83  -  [R_0402]  20.04 20.14 180 top
RA84  -  [R_0402]  20.04 21.92 180 top
RA130  -  [R_0402]  33.06 21.47 180 top
RA153  -  [R_0402]  28.48 26.82 270 top
RA165  -  [R_0402]  21.82 20.14 180 top
RA166  -  [R_0402]  21.82 21.03 180 top
RA1109  -  [R_0402]  16.73 23.37 90 top
RC1  -  [R_0402]  132.3 97.3 270 bottom
RC2  -  [R_0402]  133.19 96.54 270 bottom
RC3  -  [R_0402]  125.45 97.04 90 bottom
RC4  -  [R_0402]  146 98.24 0 bottom
RC5  -  [R_0402]  131.28 94.74 90 top
RC6  -  [R_0402]  132.17 94.74 90 top
RC7  -  [R_0402]  134.9 98.74 90 bottom
RC8  -  [R_0402]  126.34 97.04 90 bottom
RC9  -  [R_0402]  135.08 115.71 0 top
RC10  -  [R_0402]  204.05 9.8 270 bottom
RC11  -  [R_0402]  131.61 118.31 180 top
RC12  -  [R_0402]  116.23 134.46 0 top
RC13  -  [R_0402]  115.54 129.22 90 bottom
RC14  -  [R_0402]  97.96 91.07 90 bottom
RC15  -  [R_0402]  94.59 91.07 90 bottom
RC16  -  [R_0402]  96.99 90.44 180 bottom
RC17  -  [R_0402]  97.07 93.74 90 bottom
RC18  -  [R_0402]  94.4 93.74 90 bottom
RC19  -  [R_0402]  96.18 93.74 90 bottom
RC20  -  [R_0402]  97.05 92.86 0 bottom
RC21  -  [R_0402]  94.41 92.86 180 bottom
RC22  -  [R_0402]  96.19 92.86 180 bottom
RC23  -  [R_0402]  97.96 94.65 270 bottom
RC24  -  [R_0402]  93.51 94.65 270 bottom
RC25  -  [R_0402]  95.29 94.65 270 bottom
RC26  -  [R0402_0OHM]  61.63 106.21 270 top
RC27  -  [R_0402]  136.82 96.39 180 top
RC28  -  [R_0402]  148.42 108.98 0 bottom
RC29  -  [R_0402]  148.11 111.72 0 bottom
RC31  -  [R_0402]  147.87 108.79 180 top
RC32  -  [R_0402]  144.38 114.44 180 bottom
RC33  -  [R0402_0OHM]  126.98 98.18 180 top
RC34  -  [R_0402]  130.9 110.26 270 top
RC35  -  [R_0402]  134.08 97.3 270 top
RC36  -  [R_0402]  129.77 114.35 180 top
RC37  -  [R_0402]  133.44 109.17 180 bottom
RC41  -  [R0402_0OHM]  128 97.05 180 top
RC42  -  [R0402_0OHM]  134.97 96.39 90 top
RC43  -  [R0402_0OHM]  74.49 106.46 180 bottom
RC44  -  [R0402_0OHM]  74.54 104.21 180 bottom
RC45  -  [R0402_0OHM]  74.54 105.12 180 bottom
RC46  -  [R0402_0OHM]  65.94 104.36 0 bottom
RC48  -  [R_0402]  65.44 90.12 90 bottom
RC49  -  [R_0402]  63.67 90.12 90 bottom
RC50  -  [R_0402]  62.78 90.12 90 bottom
RC51  -  [R_0402]  62.78 102.27 270 bottom
RC52  -  [R_0402]  61.89 90.12 90 bottom
RC56  -  [R_0402]  58.71 101.36 90 bottom
RC57  -  [R0402_0OHM]  75.29 114.95 180 top
RC58  -  [R_0402]  89.17 119.58 0 top
RC59  -  [R0402_0OHM]  84.62 110.68 180 bottom
RC60  -  [R_0402]  88.3 120.03 90 top
RC62  -  [R_0402]  83.71 111.58 0 bottom
RC63  -  [R_0402]  89.77 112.02 180 top
RC64  -  [R_0402]  62.78 88.68 270 bottom
RC65  -  [R_0402]  83.71 109.8 0 bottom
RC66  -  [R_0402]  87.74 128.22 90 bottom
RC67  -  [R_0402]  89.56 120.93 0 top
RC68  -  [R_0402]  89.32 98.15 270 top
RC69  -  [R_0402]  90.21 98.15 270 top
RC70  -  [R_0402]  88.43 98.15 270 top
RC71  -  [R_0402]  117.75 124.03 0 top
RC72  -  [R_0402]  103.34 128.72 90 bottom
RC73  -  [R_0402]  137.13 118.45 270 bottom
RC74  -  [R_0402]  125.19 116.2 90 top
RC75  -  [R_0402]  131.04 134.81 180 bottom
RC76  -  [R_0402]  136.25 119.33 180 bottom
RC77  -  [R_0402]  129.45 118.56 180 top
RC78  -  [R_0402]  135.17 129.21 180 bottom
RC81  -  [R0402_0OHM]  129.25 133.92 90 bottom
RC84  -  [R_0402]  131.04 133.92 180 bottom
RC87  -  [R_0402]  126.27 123.7 90 top
RC88  -  [R_0402]  133.49 119.2 0 bottom
RC89  -  [R_0402]  133.14 129.21 90 bottom
RC90  -  [R_0402]  122.51 110.41 90 top
RC91  -  [R_0402]  113.75 129.3 0 bottom
RC97  -  [R_0402]  130.89 108.47 0 top
RC98  -  [R_0402]  128.54 119.45 0 top
RC99  -  [R_0402]  134.2 115.89 90 top
RC100  -  [R_0402]  136 116.6 180 top
RC101  -  [R_0402]  124.28 97.15 270 bottom
RC102  -  [R_0402]  143.85 119.66 0 bottom
RC104  -  [R_0402]  141.78 109.94 180 bottom
RC105  -  [R_0402]  132.26 130.12 270 bottom
RC106  -  [R_0402]  136.25 121.99 180 bottom
RC107  -  [R_0402]  145 111.06 0 bottom
RC108  -  [R_0402]  136.64 121.12 180 bottom
RC110  -  [R_0402]  145 111.92 0 bottom
RC111  -  [R_0402]  136.63 120.22 180 bottom
RC112  -  [R_0402]  134.6 119.33 180 top
RC113  -  [R_0402]  133.68 118.44 0 top
RC116  -  [R_0402]  133.49 118.31 0 bottom
RC118  -  [R_0402]  136.25 125.87 180 bottom
RC119  -  [R_0402]  136.25 118.44 180 bottom
RC120  -  [R_0402]  146.11 112.8 180 bottom
RC121  -  [R_0402]  136.5 114.25 180 bottom
RC122  -  [R_0402]  134.41 125.58 180 bottom
RC123  -  [R_0402]  133.49 120.09 0 bottom
RC124  -  [R_0402]  148.43 107.21 0 bottom
RC125  -  [R_0402]  148.43 108.1 0 bottom
RC126  -  [R0603_0OHM]  123.35 130.63 90 bottom
RC127  -  [R_0402]  123.21 98.19 180 top
RC128  -  [R_0402]  123.21 97.31 180 top
RC129  -  [R_0402]  123.21 96.43 180 top
RC130  -  [R_0402]  85.56 110.68 90 bottom
RC131  -  [R_0402]  124.43 130.62 90 bottom
RC132  -  [R_0402]  91.72 115.66 0 top
RC133  -  [R_0402]  122.27 131.47 270 bottom
RC134  -  [R_0402]  123.4 97.15 270 bottom
RC135  -  [R_0402]  84.62 108.91 180 bottom
RC138  -  [R_0402]  82.6 113.5 180 bottom
RC139  -  [R_0402]  108.36 129.69 270 bottom
RC140  -  [R_0402]  109.31 129.69 270 bottom
RC141  -  [R0402_0OHM]  84.12 120.03 180 bottom
RC163  -  [R_0402]  89.58 124.03 180 top
RC362  -  [R_0402]  60.99 102.26 270 bottom
RD1  -  [R0402_0OHM]  43.54 70.05 180 top
RD3  -  [R_0402]  49.48 63.45 0 top
RD4  -  [R0402_0OHM]  83.46 63.45 0 top
RD5  -  [R0402_0OHM]  83.46 62.56 0 top
RD6  -  [R_0402]  102.44 68.78 0 top
RD7  -  [R_0402]  102.44 67.89 0 top
RD8  -  [R0402_0OHM]  121.33 70.75 180 top
RD10  -  [R0402_0OHM]  162.07 62.56 0 top
RD12  -  [R_0402]  182.79 65.73 180 top
RD13  -  [R_0402]  182.78 70.48 90 top
RD14  -  [R_0402]  34.65 10.81 180 top
RD15  -  [R_0402]  43.98 10.74 180 top
RD16  -  [R_0402]  49.9 13.86 270 top
RD17  -  [R_0402]  49.01 13.86 270 top
RD18  -  [R_0402]  57.93 12.9 0 top
RD45  -  [R_0402]  54 15.9 270 top
RD46  -  [R_0402]  58.82 13.9 180 top
RD47  -  [R_0402]  65.32 16.33 90 top
RD48  -  [R_0402]  49.64 18.48 0 top
RD49  -  [R_0402]  50.62 15 0 top
RD50  -  [R_0402]  73.17 17.17 270 top
RD51  -  [R_0402]  54 14.11 270 top
RD52  -  [R_0402]  53.14 14.11 270 top
RE1  -  [R_0402]  93.77 121.8 180 top
RE2  -  [R_0402]  128.11 94.8 90 top
RE3  -  [R_0402]  197.2 53.78 90 top
RE4  -  [R_1206]  12.09 111 90 bottom
RE5  -  [R_0402]  195.42 54.7 270 top
RE7  -  [R_0402]  192.12 55.8 270 top
RE8  -  [R_0402]  199.47 38.94 0 top
RE9  -  [R_0402]  187.04 54.19 270 top
RE10  -  [R_0402]  186.15 54.19 270 top
RE11  -  [R_0402]  181.35 34.16 270 top
RE12  -  [R_0402]  179.59 40.41 180 top
RE18  -  [R_0402]  195.93 33.8 270 top
RE36  -  [R_0402]  178.58 45.86 0 top
RE37  -  [R0402_0OHM]  127.84 98.18 0 top
RE43  -  [R_0402]  179.43 41.68 180 top
RE44  -  [R0402_0OHM]  180.5 54.38 270 top
RE47  -  [R_0402]  178.27 50.35 90 top
RE49  -  [R_0402]  194.54 27.57 180 top
RE50  -  [R_0402]  50.97 105.23 180 bottom
RE60  -  [R_0402]  228.31 156.4 90 bottom
RE71  -  [R_0402]  178.52 42.57 0 top
RE326  -  [R_0402]  179.49 48.91 180 top
RG1  -  [R_0402]  74.96 45.74 270 top
RG2  -  [R_0402]  68.66 45.62 270 top
RG3  -  [R_0402]  146.87 103.22 270 bottom
RG4  -  [R_0402]  70.95 44.7 90 top
RG5  -  [R_0402]  72.93 39.01 270 top
RG6  -  [R_0402]  119.24 136.55 90 top
RG7  -  [R_0402]  174.17 98.21 90 bottom
RG8  -  [R_0402]  35.2 75.64 90 bottom
RL19  -  [R_0603]  22.19 90.31 0 top
RL20  -  [R_0603]  22.19 89.03 0 top
RL27  -  [R_0402]  42.88 79.39 0 bottom
RL31  -  [R_0402]  35.08 79.37 90 bottom
RL33  -  [R_0402]  42.97 85.79 180 top
RL34  -  [R_0402]  42.97 83.77 180 bottom
RL35  -  [R_0402]  42.97 84.83 180 top
RL37  -  [R_0402]  37.68 88.25 90 bottom
RL38  -  [R_0402]  41.43 79.75 90 bottom
RL39  -  [R_0603]  22.19 82.68 0 top
RL40  -  [R_0603]  22.19 81.41 0 top
RM11  -  [R_0402]  115.09 147.7 90 top
RM13  -  [R_0402]  115.98 148.61 270 top
RM25  -  [R0805_0OHM]  120.68 148.22 180 top
RM26  -  [R0805_0OHM]  96 148.47 180 top
RM110  -  [R_0402]  104.17 148.68 270 top
RP1  -  [RP_0804_8P4R]  16.99 118.41 180 bottom
RP36  -  [RP_0804_8P4R]  189.4 54.24 90 top
RP37  -  [RP_0804_8P4R]  138.97 115.16 0 bottom
RP39  -  [RP_0804_8P4R]  140.12 119.46 180 bottom
RP40  -  [RP_0804_8P4R]  138.46 112.04 0 bottom
RP41  -  [RP_0804_8P4R]  142.34 111.29 0 bottom
RP42  -  [RP_0804_8P4R]  148.18 112.73 180 top
RP43  -  [RP_0804_8P4R]  143.11 122.31 180 bottom
RP44  -  [RP_0804_8P4R]  86.46 123.7 180 bottom
RP45  -  [RP_0804_8P4R]  74.94 111.4 180 top
RP46  -  [RP_0804_8P4R]  60.6 89.48 90 bottom
RP47  -  [RP_0804_8P4R]  175.62 105.86 90 top
RP48  -  [RP_0804_8P4R]  86.89 110.99 0 bottom
RP49  -  [RP_0804_8P4R]  138.46 109.24 0 bottom
RP50  -  [RP_0804_8P4R]  132.18 111.34 180 top
RP51  -  [RP_0804_8P4R]  130.95 130.05 90 bottom
RP52  -  [RP_0804_8P4R]  127.96 130.64 90 bottom
RP53  -  [RP_0804_8P4R]  135.73 123.28 0 bottom
RP54  -  [RP_0804_8P4R]  132.18 114.13 180 top
RP55  -  [RP_0804_8P4R]  139.59 97.45 270 top
RP56  -  [RP_0804_8P4R]  200.06 175.47 180 top
RP57  -  [RP_0804_8P4R]  196.82 165.69 180 top
RP60  -  [RP_0804_8P4R]  184 105.92 90 top
RR1  -  [R_0402]  175 18.07 270 top
RR2  -  [R_0402]  178.21 27.11 90 top
RR3  -  [R_0402]  180.88 20.94 0 top
RS6  -  [R_0402]  222.67 126.3 0 bottom
RS7  -  [R_0402]  215.88 57.86 0 top
RS8  -  [R_0402]  215.88 58.76 0 top
RV1  -  [R_0402]  218.6 143.09 270 bottom
RV2  -  [R_0402]  218.52 140.41 0 bottom
RV3  -  [R_0402]  218.46 126.44 0 bottom
RV4  -  [R_0402]  218.46 124.66 0 bottom
RV5  -  [R_0402]  201.41 133.68 180 bottom
RV6  -  [R_0402]  200.5 131.9 0 bottom
RV7  -  [R_0402]  218.71 124.66 0 top
RV8  -  [R_0402]  219.62 126.44 180 top
RV9  -  [R_0402]  206.4 142.62 90 top
RV10  -  [R_0402]  204.63 143.53 270 top
RV11  -  [R_0402]  201.46 131.86 180 top
RV12  -  [R_0402]  200.55 129.68 0 top
RV13  -  [R_0402]  212.64 102.05 180 bottom
RV14  -  [R_0402]  211.73 100.28 0 bottom
RV15  -  [R_0402]  206.15 101.81 270 bottom
RV16  -  [R_0402]  204.37 100.9 90 bottom
RV17  -  [R_0402]  201.22 111.88 180 top
RV19  -  [R_0402]  200.31 113.66 0 top
RV20  -  [R_0402]  214.53 100.1 270 top
RV21  -  [R_0402]  212.75 99.18 90 top
RV22  -  [R_0402]  218.46 120.09 0 top
RV23  -  [R_0402]  218.46 118.31 0 top
RV24  -  [R_0402]  201.22 111.88 180 bottom
RV25  -  [R_0402]  172.11 138.19 90 top
RV26  -  [R_0402]  172.11 138.19 90 bottom
RV27  -  [R_0402]  200.31 113.66 0 bottom
RV28  -  [R_0402]  158.13 150.31 0 top
RV29  -  [R_0402]  169 139.1 270 bottom
RV30  -  [R_0402]  191.35 138.12 90 bottom
RV31  -  [R_0402]  191.35 138.12 90 top
RV32  -  [R_0402]  200.96 157.05 180 top
RV33  -  [R_0402]  200.04 155.27 0 top
RV34  -  [R_0402]  159.05 152.09 180 top
RV35  -  [R_0402]  177.07 157.3 270 bottom
RV36  -  [R_0402]  178.85 156.39 90 bottom
RV37  -  [R_0402]  169.89 138.19 90 bottom
RV38  -  [R_0402]  177.07 157.3 270 top
RV39  -  [R_0402]  187.35 139.04 270 bottom
RV40  -  [R_0402]  200.5 155.98 270 bottom
RV41  -  [R_0402]  202.34 155.06 90 bottom
RV42  -  [R_0402]  172.62 126.87 90 top
RV43  -  [R_0402]  173.51 126.87 90 top
RV44  -  [R_0402]  186.16 127.26 180 top
RV45  -  [R_0402]  186.16 128.15 180 top
RV46  -  [R_0402]  186.39 126.25 0 top
RV47  -  [R_0402]  190.85 126.83 270 top
RV48  -  [R_0402]  187.47 115.77 0 top
RV49  -  [R_0402]  190.16 115.77 180 top
RV54  -  [R0603_0OHM]  32.73 12.77 180 top
RV59  -  [R0603_0OHM]  19.65 25.79 270 top
RV64  -  [R_0402]  178.32 105.98 0 top
RV66  -  [R_0402]  161.72 112.54 180 bottom
RV67  -  [R_0402]  194.34 99.56 90 bottom
RV68  -  [R_0402]  194.34 102.25 270 bottom
RV69  -  [R_0402]  191.8 99.56 90 bottom
RV70  -  [R_0402]  191.8 102.25 270 bottom
RV71  -  [R_0402]  192.88 99.56 90 bottom
RV73  -  [R_0402]  190.86 102.24 180 bottom
RV74  -  [R_0402]  189.97 98.36 180 bottom
RV75  -  [R_0402]  181.7 96.64 90 bottom
RV76  -  [R_0402]  182.59 96.64 90 bottom
RV81  -  [R_0402]  183.48 96.64 90 bottom
RV82  -  [R_0402]  184.37 96.64 90 bottom
RV83  -  [R_0402]  185.26 96.64 90 bottom
RV84  -  [R_0402]  158.51 112.53 0 bottom
RV85  -  [R_0402]  187.29 105.92 90 top
RV89  -  [R_0402]  181.64 104.41 270 top
RV90  -  [R_0402]  179.92 93.4 90 top
RV91  -  [R_0402]  175.16 92.54 270 top
RV93  -  [R_0402]  185.02 100.46 180 bottom
RV95  -  [R_0402]  185.02 101.35 180 bottom
RV96  -  [R_0402]  175.36 96.35 270 bottom
RV97  -  [R_0402]  171.43 102.05 180 bottom
RV98  -  [R_0402]  175.36 93.68 90 bottom
RV103  -  [R_0805]  168.3 127.86 270 top
RV105  -  [R_0402]  175.54 158.49 90 bottom
RV107  -  [R_0402]  189.26 92.13 90 bottom
RV108  -  [R_0402]  189.26 93.91 90 bottom
RV109  -  [R_0402]  173.31 92.59 0 bottom
RV118  -  [R0402_0OHM]  160.56 104.42 270 top
RV119  -  [R0402_0OHM]  182.54 99.13 180 bottom
RV120  -  [R0402_0OHM]  157.45 105.98 90 top
RV121  -  [R0402_0OHM]  186.86 99.2 180 bottom
RV122  -  [R_0402]  183.22 102.25 270 bottom
RV123  -  [R_0402]  173.12 104.27 0 top
RV124  -  [R0402_0OHM]  156.56 103.5 90 top
RV125  -  [R_0402]  178.07 110.56 0 top
RV126  -  [R0402_0OHM]  157.57 100.33 90 top
RV127  -  [R_0402]  161.84 107.83 180 bottom
RV133  -  [R_0402]  169.69 115.83 0 top
RV136  -  [R_0402]  193.44 93.35 0 top
RV137  -  [R_0402]  192.44 91.51 180 top
RV138  -  [R_0402]  210.91 99.05 90 top
RV139  -  [R_0402]  162.03 130.63 180 bottom
RV140  -  [R_0402]  162.02 131.57 180 bottom
RV141  -  [R_0402]  196.14 101.49 90 bottom
RV142  -  [R_0402]  197.96 105.04 90 bottom
RV143  -  [R_0402]  209.96 99.97 270 top
RV144  -  [R_0402]  207.61 99.37 90 top
RV145  -  [R_0402]  206.66 99.37 90 top
RV146  -  [R_0402]  161.11 129.74 0 bottom
RV147  -  [R_0402]  161.11 132.46 0 bottom
RV148  -  [R_0402]  197.09 103.27 90 bottom
RV149  -  [R_0402]  197.07 105.95 270 bottom
RV162  -  [R_0402]  200.55 127.39 0 top
RV163  -  [R_0402]  200.5 129.68 0 bottom
RV169  -  [R_0402]  200.31 110.55 0 top
RV171  -  [R_0402]  200.31 110.55 0 bottom
RV181  -  [R_0402]  178.85 156.39 90 top
RV183  -  [R_0402]  169.89 138.19 90 top
RV184  -  [R_0402]  168.11 139.1 270 top
RV185  -  [R_0402]  158.13 149.43 0 top
RV186  -  [R_0402]  159.05 147.65 180 top
RV191  -  [R_0402]  181.51 156.27 90 top
RV192  -  [R_0402]  179.73 156.27 90 top
RV193  -  [R_0402]  189.13 138.12 90 top
RV194  -  [R_0402]  187.35 139.04 270 top
RV195  -  [R_0402]  182.4 157.06 270 bottom
RV196  -  [R_0402]  180.62 156.14 90 bottom
RV197  -  [R_0402]  189.13 138.12 90 bottom
RV198  -  [R_0402]  171.23 119.44 90 top
RV199  -  [R_0402]  182.54 94.36 180 top
RV201  -  [R_0402]  154.99 110.19 270 top
RV202  -  [R_0402]  173.4 115.72 180 top
RV203  -  [R_0402]  164.49 98.99 270 top
RV204  -  [R_0402]  172.82 112.33 180 top
RV206  -  [R_0402]  176.25 125.78 180 top
RV207  -  [R_0402]  166.22 112.08 180 top
RV215  -  [R_0402]  179.11 107.45 180 top
RV234  -  [R_0603]  165.26 126.5 180 top
RV235  -  [R_0402]  175.92 101.27 90 bottom
RV236  -  [R_0402]  174.91 102.19 270 bottom
RV237  -  [R_0402]  166.38 98.99 270 top
RV238  -  [R_0402]  168.24 98.07 90 top
RV239  -  [R_0402]  158.4 109.27 90 top
RV240  -  [R_0402]  159.28 110.19 270 top
RV241  -  [R_0402]  160.81 112.54 270 top
RV242  -  [R_0402]  158.52 111.62 90 top
RV243  -  [R_0402]  156.87 109.27 90 top
RV244  -  [R_0402]  154.33 115.14 270 top
RV245  -  [R_0402]  153.38 115.14 270 top
RV246  -  [R_0402]  171.36 110.75 180 top
RV247  -  [R_0402]  167.02 108.4 0 top
RV248  -  [R0402_0OHM]  167.02 107.45 0 top
RV250  -  [R_0402]  188.16 102.24 0 bottom
RV251  -  [R_0402]  177.13 101.27 90 bottom
RV252  -  [R_0402]  178.08 101.27 90 bottom
RX1  -  [R_0402]  16.73 97.23 270 top
RX2  -  [R_0402]  218.98 176.27 90 top
RX3  -  [R_0402]  218.09 177.19 270 top
RX4  -  [R0805_0OHM]  202.05 165.89 180 bottom
RX5  -  [R_0402]  198.71 166.72 0 top
RX6  -  [R_0402]  199.33 163.14 90 bottom
RX7  -  [R0402_0OHM]  216.88 166.84 270 top
RX8  -  [R_0402]  215.99 166.84 270 top
RX9  -  [R_0402]  219.82 167.02 180 bottom
RX18  -  [R_0402]  211.36 175.88 0 top
RX19  -  [R0402_0OHM]  214.01 176.74 270 top
RX20  -  [R0402_0OHM]  212.27 176.77 180 top
RX21  -  [R_0402]  218.98 165.73 90 top
RX22  -  [R_0402]  219.87 165.73 90 top
RX23  -  [R_0402]  213.12 176.74 270 top
RX24  -  [R_0402]  15.84 97.23 270 top
RX25  -  [R_0402]  197.63 171.1 180 top
RX26  -  [R_0402]  203.99 165.25 270 bottom
RX27  -  [R0603_0OHM]  217.64 173.56 0 top
RX28  -  [R_0603]  29.62 96.58 180 top
RX29  -  [R_0603]  29.62 95.15 180 top
RX30  -  [R_0402]  196.71 172.35 0 top
RX31  -  [R_0402]  198.45 163.14 90 bottom
RX33  -  [R_0402]  204.68 177.37 0 top
RX35  -  [R_0402]  198.61 172.67 180 bottom
RX36  -  [R_0402]  206.53 165.25 270 bottom
RX37  -  [R_0402]  201.02 172.25 0 bottom
RX38  -  [R_0402]  206.53 171.26 0 bottom
RX39  -  [R_0402]  201.02 171.36 0 bottom
RX40  -  [R_0402]  206.53 170.37 0 bottom
RX41  -  [R_0402]  201.02 170.47 0 bottom
RX42  -  [R_0402]  206.53 169.48 0 bottom
RX43  -  [R_0402]  201.02 169.58 0 bottom
RX44  -  [R_0402]  206.53 168.59 0 bottom
RX45  -  [R_0402]  201.02 168.69 0 bottom
RX46  -  [R_0402]  206.53 167.7 0 bottom
RX47  -  [R_0402]  201.02 167.8 0 bottom
RX48  -  [R_0402]  206.53 166.81 0 bottom
RX49  -  [R_0402]  205.64 165.25 270 bottom
RX50  -  [R_0402]  213.57 162 0 bottom
RX51  -  [R_0402]  207.42 164.34 90 bottom
RX52  -  [R_0402]  198.61 171.78 180 bottom
RX53  -  [R_0402]  208.74 176.98 0 top
RX168  -  [R_0402]  197.64 176.81 270 bottom
RX169  -  [R_0402]  197.64 174.11 90 bottom
RX170  -  [R_0402]  198.53 175.89 90 bottom
RX171  -  [R_0402]  198.53 175.03 270 bottom
SW1  -  [SW_SMT1-05-A_4P]  196.77 27.43 90 top
SW2  -  [SW_SMT1-05-A_4P]  202.92 39.99 180 bottom
T1  -  [TPC12]  12.94 104.49 0 top
T2  -  [TPC12]  26.25 104.9 90 top
T38  -  [TPC12]  116.56 113.31 0 top
T39  -  [TPC12]  89.99 117.2 180 bottom
T40  -  [TPC12]  91.57 117.29 0 top
T41  -  [TPC12]  94.78 118.1 0 top
T42  -  [TPC12]  88.58 117.71 180 bottom
T43  -  [TPC12]  93.47 117.24 0 top
T44  -  [TPC12]  92.41 112.57 0 top
T45  -  [TPC12]  94.26 112.47 0 top
T46  -  [TPC12]  95.63 112.98 0 top
T47  -  [TPC12]  90.01 110.56 180 bottom
T48  -  [TPC12]  93.94 114.11 0 top
T49  -  [TPC12]  93.57 111.04 0 top
T50  -  [TPC12]  94.91 116.78 0 top
T51  -  [TPC12]  94.26 115.45 0 top
T53  -  [TPC12]  122.01 120.67 0 top
T55  -  [TPC12]  122.3 109.29 0 top
T56  -  [TPC12]  124.77 114.54 0 top
T58  -  [TPC12]  122.63 112.48 0 top
T59  -  [TPC12]  125.57 113.45 0 top
T78  -  [TPC12]  182.53 111.87 270 top
T79  -  [TPC12]  174.96 110.17 270 top
T80  -  [TPC12]  169.67 116.79 270 top
T81  -  [TPC12]  171.16 116.83 270 top
T82  -  [TPC12]  162.22 134.29 90 bottom
T83  -  [TPC12]  193.37 102.51 90 bottom
T84  -  [TPC12]  166.03 101.83 90 bottom
T85  -  [TPC12]  161.47 113.56 180 bottom
T86  -  [TPC12]  163.56 114.2 180 bottom
T87  -  [TPC12]  163.1 112.46 180 bottom
T88  -  [TPC12]  161.92 114.88 180 bottom
T89  -  [TPC12]  163.7 116.17 180 bottom
T90  -  [TPC12]  172.55 108.94 0 top
T91  -  [TPC12]  173.03 110.3 0 top
T94  -  [TPC12]  40.69 78.59 180 bottom
T95  -  [TPC12]  40.17 81.11 180 bottom
T96  -  [TPC12]  40 79.82 180 bottom
T97  -  [TPC12]  133.76 112.72 180 bottom
T98  -  [TPC12]  135.33 112.8 180 bottom
T99  -  [TPC12]  133.02 111.34 180 bottom
T102  -  [TPC12]  126.95 111.57 0 top
T103  -  [TPC12]  136.3 98.31 0 top
T104  -  [TPC12]  128.02 110.63 0 top
T105  -  [TPC12]  128.09 109.3 0 top
T106  -  [TPC12]  133.57 106.39 180 bottom
T107  -  [TPC12]  123.72 111.07 0 top
T111  -  [TPC12]  88.85 122.52 0 top
T112  -  [TPC12]  88.61 121.74 180 bottom
T113  -  [TPC12]  94.44 119.49 0 top
T114  -  [TPC12]  90.52 122.31 0 top
T115  -  [TPC12]  93.34 118.86 0 top
T116  -  [TPC12]  94.56 120.77 0 top
T117  -  [TPC12]  127.8 112.55 0 top
T118  -  [TPC12]  123.23 99.85 0 top
T119  -  [TPC12]  124.12 105.74 0 top
T120  -  [TPC12]  122.02 123.55 0 top
T121  -  [TPC12]  123.5 125.52 0 top
T124  -  [TPC12]  128.98 117.52 0 top
T125  -  [TPC12]  133.45 114.45 180 bottom
T126  -  [TPC12]  129.63 109.45 0 top
T127  -  [TPC12]  128.36 107.9 0 top
T128  -  [TPC12]  135.2 104.82 180 bottom
T129  -  [TPC12]  116.4 119.3 0 top
T130  -  [TPC12]  115.59 117.82 0 top
T131  -  [TPC12]  115.88 116.25 0 top
T132  -  [TPC12]  102.65 99.91 180 bottom
T133  -  [TPC12]  124.26 117.08 0 top
T134  -  [TPC12]  103.76 101.2 180 bottom
T135  -  [TPC12]  121.85 125.4 0 top
T136  -  [TPC12]  133.63 108.15 180 bottom
T137  -  [TPC12]  124.35 107.12 0 top
T138  -  [TPC12]  118.08 122.82 0 top
T139  -  [TPC12]  134.75 98.26 0 top
T140  -  [TPC12]  117.44 121.61 0 top
T141  -  [TPC12]  124.97 98.11 0 top
T142  -  [TPC12]  123.5 101.51 0 top
T143  -  [TPC12]  118.65 119.33 0 top
T144  -  [TPC12]  124.46 99.1 180 bottom
T145  -  [TPC12]  123.6 100.65 180 bottom
T146  -  [TPC12]  89.13 97.09 180 bottom
T147  -  [TPC12]  87.58 96.36 180 bottom
T148  -  [TPC12]  88.62 125.25 180 bottom
T149  -  [TPC12]  88.53 123.97 180 bottom
T150  -  [TPC12]  104.55 128.92 180 bottom
T151  -  [TPC12]  98.86 127.41 180 bottom
T152  -  [TPC12]  99.98 128.72 180 bottom
T153  -  [TPC12]  88.61 119.01 180 bottom
T154  -  [TPC12]  92.06 118.67 0 top
T155  -  [TPC12]  115.58 114.73 0 top
T156  -  [TPC12]  117.42 114.89 0 top
T157  -  [TPC12]  88.79 98.96 180 bottom
T158  -  [TPC12]  93.18 128.89 180 bottom
T159  -  [TPC12]  131.35 128.6 180 bottom
T160  -  [TPC12]  120.29 117.61 0 top
T161  -  [TPC12]  133.29 124.05 180 bottom
T162  -  [TPC12]  120.03 116.12 0 top
T163  -  [TPC12]  134.41 124.69 180 bottom
T164  -  [TPC12]  117.64 120.22 0 top
T165  -  [TPC12]  120.14 121.05 0 top
T166  -  [TPC12]  90.33 99.36 180 bottom
T167  -  [TPC12]  133.57 126.65 180 bottom
T168  -  [TPC12]  133.5 128.03 180 bottom
T169  -  [TPC12]  89.4 129.86 180 bottom
T170  -  [TPC12]  88.58 127.44 180 bottom
T171  -  [TPC12]  133.7 104.66 180 bottom
T172  -  [TPC12]  134.09 102.35 180 bottom
T173  -  [TPC12]  90.68 97.6 180 bottom
T174  -  [TPC12]  126.86 113.55 0 top
T175  -  [TPC12]  126.94 118.35 0 top
T176  -  [TPC12]  126.28 119.55 0 top
T177  -  [TPC12]  127.66 117.24 0 top
T178  -  [TPC12]  125.25 118.36 0 top
T179  -  [TPC12]  132.08 120.33 180 bottom
T180  -  [TPC12]  132.43 121.57 180 bottom
T181  -  [TPC12]  134.41 122.04 180 bottom
T182  -  [TPC12]  126.18 109.54 0 top
T183  -  [TPC12]  151.36 81.11 180 bottom
T184  -  [TPC12]  153.18 81.11 180 bottom
T185  -  [TPC12]  153.11 78.7 180 bottom
T186  -  [TPC12]  151.34 78.66 180 bottom
TL2  -  [TAIMA_IH-115-F_24P]  29.41 92.84 270 bottom
U1  -  [P_M74VHC1GT125DF2G_SC70_5P]  14.38 108.2 90 top
U2  -  [P_M74VHC1GT125DF2G_SC70_5P]  14.38 112.01 90 top
U4  -  [IT6511FN_QFN56_7X7]  17.57 100.4 90 bottom
U2301  -  [TPS22966DPUR_SON14_2X3]  97.81 28.39 180 bottom
U2302  -  [W25Q64FVSSIG_SO8]  150.53 85.5 90 bottom
U2303  -  [74AUP1G07GW_TSSOP5]  43.47 66.04 0 top
U2304  -  [TPS22966DPUR_SON14_2X3]  140.75 22.1 0 top
UA1  -  [ALC3221-CG_MQFN48_6X6]  30.06 18.45 90 top
UC1  -  [HASWELL-MCP-E-ULT_BGA_1168P-T]  130.28 125.56 0 bottom
UC3  -  [MC74VHC1G08DFT2G_SC70-5]  148.25 105.93 180 top
UC4  -  [74CBTLV3126BQ_DHVQFN14_2P5X3]  71.1 106.53 270 bottom
UD1  -  [MC74VHC1G08DFT2G_SC70-5]  49.64 17.39 270 top
UE1  -  [KB9012QF-A2_LQFP128_14X14]  183.19 35.68 0 top
UE2  -  [SN74LVC1G06DCKR_SC70-5]  178.13 52.42 0 top
UE3  -  [G993P1UF_SOP8]  46.26 103.37 0 bottom
UG1  -  [SLG3NB274VTR_TQFN16_2X3]  70.63 40.63 0 top
UI2  -  [AP2301MPG-13_MSOP8]  28.53 52.06 90 top
UI3  -  [AP2301MPG-13_MSOP8]  25.41 61.43 90 top
UI4  -  [AP2301MPG-13_MSOP8]  20.34 30.98 90 top
UI5  -  [AP2301MPG-13_MSOP8]  205.87 42.12 0 top
UL1  -  [RTL8106E-CG_QFN32_4X4]  35.67 82.87 90 bottom
UL2  -  [APL3512ABI-TRG_SOT23-5]  49.51 83.26 270 bottom
UR1  -  [RTS5179-GR_QFN24_4X4]  175.82 21.39 0 top
UV1  -  [2160809000A11SEYMOU_FCBGA_962P]  192.86 133.09 180 bottom
UV3  -  [K4G20325FC-HC05_FBGA_170P]  195.6 152.78 270 top
UV4  -  [K4G20325FC-HC05_FBGA_170P]  162.28 152.85 270 bottom
UV5  -  [K4G20325FC-HC05_FBGA_170P]  175.09 152.85 270 top
UV6  -  [K4G20325FC-HC05_FBGA_170P]  182.79 152.78 270 bottom
UV7  -  [K4G20325FC-HC05_FBGA_170P]  215.16 126.71 180 top
UV8  -  [K4G20325FC-HC05_FBGA_170P]  215.16 139.51 180 bottom
UV9  -  [K4G20325FC-HC05_FBGA_170P]  214.97 106.31 180 top
UV10  -  [K4G20325FC-HC05_FBGA_170P]  214.97 119.11 180 bottom
UV13  -  [MC74VHC1G08DFT2G_SC70-5]  158.91 109.09 90 bottom
UV14  -  [ADM1032ARMZ-2REEL_MSOP8]  178.55 94.25 180 bottom
UX1  -  [APL3512ABI-TRG_SOT23-5]  215.68 168.08 0 top
UX2  -  [MC74VHC1G08DFT2G_SC70-5]  210.43 161.22 90 bottom
UX4  -  [RTD2136R-CG_QFN48_6X6]  201.27 172.58 270 top
X1  -  [Y_7V27000050_4P]  29.66 98.02 90 bottom
YC1  -  [Y_Q13FC1350000_2P]  146.86 100.72 0 bottom
YC2  -  [Y_X3G024000DC1H_4P]  115.52 135.76 0 top
YG1  -  [Y_FSX3M-25PM20FDO_4P]  63.7 39.53 0 top
YL2  -  [Y_FSX3M-25PM20FDO_4P]  36.78 78.15 0 bottom
YV1  -  [Y_7V27000011_4P]  172.39 98.21 180 bottom

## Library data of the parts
